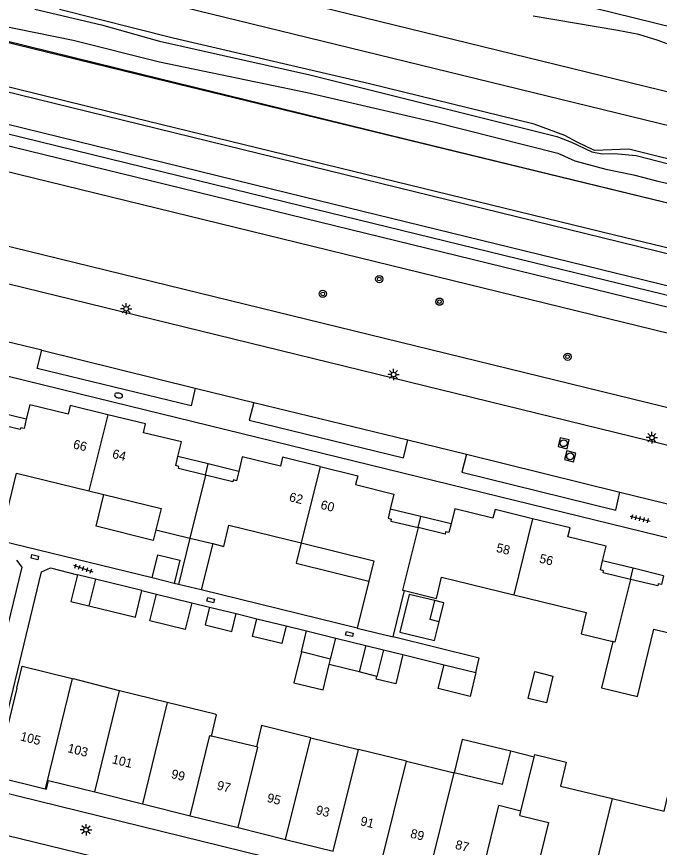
# Model space of a CAD drawing. Extents: x 125000 to 129004, y 397500 to 399008.
# Drawn here: x 126519.7 to 126590.3, y 398569.4 to 398660.6 of the extents above; entities that cross this region are included whole.
import ezdxf

# ---------------------------------------------------------------- set-up
doc = ezdxf.new("R2010")
doc.units = 0
for name, color, linetype in [('gg-afsc-erfafscheiding', 7, 'Continuous'), ('gg-afsc-hekwerk', 7, 'Continuous'), ('gg-anno-huisnummerreeks BGT', 7, 'Continuous'), ('gg-aspt-spoorlijn', 7, 'Continuous'), ('gg-bbg-bijgebouw', 7, 'Continuous'), ('gg-bbg-gedigitaliseerde bebouwing', 7, 'Continuous'), ('gg-bbg-gedigitaliseerde bijgebouw', 7, 'Continuous'), ('gg-bbg-hoofdgebouw', 7, 'Continuous'), ('gg-bbg-luifel en loopbrug', 7, 'Continuous'), ('gg-bbg-tussenscheiding', 7, 'Continuous'), ('gg-knt-BGT kruinlijn', 7, 'Continuous'), ('gg-knt-verharding', 7, 'Continuous'), ('gg-knt-verharding nz', 7, 'Continuous'), ('gg-kntw-bovenkant insteek waterloop', 7, 'Continuous'), ('gg-kntw-waterlijn', 7, 'Continuous'), ('gt-grn-groengrens', 7, 'Continuous'), ('gt-symb-boom', 7, 'Continuous'), ('gt-symb-brandkraan', 7, 'Continuous'), ('gt-symb-kolk center center', 7, 'Continuous'), ('gt-symb-lichtmast', 7, 'Continuous'), ('gt-symb-rioolschacht', 7, 'Continuous'), ('gt-symb-tegel verharding', 7, 'Continuous'), ('gx-grn-maaiveld', 7, 'Continuous')]:
    doc.layers.add(name, color=color, linetype=linetype)

# ---------------------------------------------------------------- blocks, each defined once
blk = doc.blocks.new('gt0-LMAST')
at = {"layer": 'gt-symb-lichtmast'}
for p, q in [((-0.182, 0.173), (-0.447, 0.438)), ((-0.005, 0.246), (-0.005, 0.621)), ((0.172, 0.173), (0.437, 0.438)), ((-0.255, -0.004), (-0.63, -0.004)), ((-0.182, -0.181), (-0.447, -0.446)), ((-0.005, -0.254), (-0.005, -0.629)), ((0.437, -0.446), (0.172, -0.181)), ((0.245, -0.004), (0.62, -0.004))]:
    blk.add_line(p, q, dxfattribs=at)
blk.add_circle((-0.005, -0.004), 0.25, dxfattribs=at)
blk = doc.blocks.new('gt0-KOLKCC')
at = {"layer": 'gt-symb-kolk center center'}
blk.add_lwpolyline([(-0.375, 0.2), (0.375, 0.2), (0.375, -0.2), (-0.375, -0.2)], close=True, dxfattribs=at)
blk = doc.blocks.new('gt0-TEG1')
at = {"layer": 'gt-symb-tegel verharding'}
for p, q in [((-1.125, 0), (1.125, 0)), ((-0.9, -0.25), (-0.9, 0.25)), ((-0.45, -0.25), (-0.45, 0.25)), ((0, -0.25), (0, 0.25)), ((0.45, -0.25), (0.45, 0.25)), ((0.9, -0.25), (0.9, 0.25))]:
    blk.add_line(p, q, dxfattribs=at)
blk = doc.blocks.new('gt0-RS')
at = {"layer": 'gt-symb-rioolschacht'}
blk.add_lwpolyline([(-0.5, -0.5), (0.5, -0.5), (0.5, 0.5), (-0.5, 0.5)], close=True, dxfattribs=at)
blk.add_circle((0, 0), 0.375, dxfattribs=at)
blk = doc.blocks.new('gt0-BOOM')
at = {"layer": 'gt-symb-boom'}
for radius in [0.4, 0.2]:
    blk.add_circle((0, 0), radius, dxfattribs=at)
blk = doc.blocks.new('gt0-BR')
at = {"layer": 'gt-symb-brandkraan'}
for centre, radius, start, end in [((-0.244, 0), 0.206, 107.56694, 252.43307), ((0.599, -2.664), 3, 106.89205, 107.56694), ((0, -0.691), 0.938, 73.10799, 106.89205), ((-0.599, -2.664), 3, 72.43309, 73.10799), ((0.244, 0), 0.206, 287.56695, 72.43309), ((0.599, 2.664), 3, 252.43307, 253.10797), ((0, 0.691), 0.938, 253.10797, 286.89206), ((-0.599, 2.664), 3, 286.89206, 287.56695)]:
    blk.add_arc(centre, radius, start, end, dxfattribs=at)

msp = doc.modelspace()

# ---------------------------------------------------------------- linework, layer by layer
at = {"layer": 'gg-afsc-erfafscheiding'}
for p, q in [((126534.591, 398598.969), (126517.906, 398603.051)), ((126537.488, 398598.26), (126537.02, 398598.375)), ((126557.101, 398593.463), (126539.996, 398597.647)), ((126533.482, 398597.58), (126535.067, 398597.191)), ((126538.952, 398596.239), (126540.894, 398595.763)), ((126543.808, 398595.048), (126546.091, 398594.488)), ((126549.296, 398593.702), (126551.542, 398593.151)), ((126562.128, 398590.554), (126566.636, 398589.448))]:
    msp.add_line(p, q, dxfattribs=at)
for points in [[(126519.71, 398600.927), (126520.306, 398600.163), (126514.596, 398576.815), (126514.448, 398576.329)], [(126516.671, 398575.792), (126522.462, 398599.626), (126523.459, 398600.086), (126526.396, 398599.321)], [(126570.132, 398588.591), (126570.497, 398590.181), (126561.049, 398592.494)]]:
    msp.add_lwpolyline(points, dxfattribs=at)
at = {"layer": 'gg-afsc-hekwerk'}
msp.add_line((126650.035, 398603.269), (126463.135, 398648.945), dxfattribs=at)
for points in [[(126940.304, 398557.446), (126936.567, 398555.946), (126917.248, 398560.73), (126904.597, 398563.825), (126899.09, 398565.16), (126880.395, 398569.39), (126871.244, 398571.606), (126843.113, 398578.463), (126834.208, 398580.63), (126815.394, 398585.233), (126798.941, 398589.25), (126780.443, 398593.783), (126766.856, 398597.149), (126719.035, 398608.855), (126669.566, 398620.853), (126627.707, 398631.15), (126610.862, 398635.296), (126560.721, 398647.519), (126548.679, 398650.481), (126533.314, 398654.267), (126513.26, 398659.192), (126493.962, 398663.952), (126437.616, 398677.701), (126422.794, 398681.33)], [(126461.9, 398657.483), (126656.147, 398609.937), (126654.287, 398602.23)]]:
    msp.add_lwpolyline(points, dxfattribs=at)
at = {"layer": 'gg-aspt-spoorlijn'}
for points in [[(126178.191, 398753.482), (126243.646, 398737.457), (126261.198, 398733.101), (126493.406, 398676.338), (126551.442, 398662.053), (126716.835, 398621.637), (126769.514, 398608.681), (126782.186, 398605.654), (126808.742, 398599.06), (126873.678, 398583.156), (126950.767, 398564.393)], [(126177.482, 398749.914), (126237.61, 398735.207), (126282.856, 398724.218), (126424.134, 398689.529), (126477.102, 398676.62), (126493.227, 398672.592), (126610.16, 398643.995), (126627.72, 398639.762), (126691.525, 398624.102), (126709.464, 398619.631), (126949.829, 398560.886)]]:
    msp.add_lwpolyline(points, dxfattribs=at)
at = {"layer": 'gg-bbg-bijgebouw'}
msp.add_line((126528.382, 398598.831), (126526.396, 398599.321), dxfattribs=at)
for points in [[(126526.396, 398599.321), (126525.681, 398596.371), (126527.673, 398595.889)], [(126576.602, 398588.69), (126578.591, 398588.197), (126577.86, 398585.247), (126575.87, 398585.741), (126576.602, 398588.69)]]:
    msp.add_lwpolyline(points, dxfattribs=at)
at = {"layer": 'gg-bbg-gedigitaliseerde bebouwing'}
for p, q in [((126573.052, 398576.282), (126573.95, 398579.944)), ((126576.517, 398579.315), (126573.95, 398579.944)), ((126576.517, 398579.315), (126576.588, 398579.606)), ((126567.736, 398577.595), (126567.582, 398577.633)), ((126573.052, 398576.282), (126567.736, 398577.595)), ((126570.261, 398564.268), (126572.642, 398573.978)), ((126575.067, 398573.384), (126572.642, 398573.978)), ((126574.948, 398572.898), (126575.067, 398573.384))]:
    msp.add_line(p, q, dxfattribs=at)
at = {"layer": 'gg-bbg-gedigitaliseerde bijgebouw'}
for p, q in [((126533.482, 398597.58), (126528.382, 398598.831)), ((126537.02, 398598.375), (126534.591, 398598.969)), ((126535.067, 398597.191), (126538.952, 398596.239)), ((126540.894, 398595.763), (126543.808, 398595.048)), ((126546.091, 398594.488), (126549.296, 398593.702)), ((126550.975, 398590.842), (126551.542, 398593.151)), ((126551.542, 398593.151), (126554.746, 398592.365)), ((126554.746, 398592.365), (126558.049, 398591.555)), ((126558.049, 398591.555), (126557.335, 398588.647)), ((126554.18, 398590.055), (126550.975, 398590.842)), ((126559.991, 398591.078), (126559.277, 398588.17)), ((126559.991, 398591.078), (126562.128, 398590.554)), ((126554.033, 398589.457), (126554.18, 398590.055)), ((126557.335, 398588.647), (126554.033, 398589.457)), ((126566.636, 398589.448), (126570.132, 398588.591))]:
    msp.add_line(p, q, dxfattribs=at)
for points in [[(126534.591, 398598.969), (126535.211, 398601.496), (126537.639, 398600.901), (126537.02, 398598.375)], [(126527.673, 398595.889), (126532.774, 398594.655), (126533.482, 398597.58)], [(126538.952, 398596.239), (126538.237, 398593.325), (126534.352, 398594.278), (126535.067, 398597.191)], [(126565.638, 398596.475), (126562.812, 398597.167), (126561.796, 398593.019)], [(126566.102, 398594.164), (126565.13, 398594.401), (126565.638, 398596.475)], [(126540.894, 398595.763), (126540.418, 398593.82), (126543.332, 398593.106), (126543.808, 398595.048)], [(126549.296, 398593.702), (126548.82, 398591.759), (126545.615, 398592.545), (126546.091, 398594.488)], [(126561.796, 398593.019), (126565.594, 398592.09), (126566.102, 398594.164)], [(126562.128, 398590.554), (126561.342, 398587.349), (126559.204, 398587.873), (126559.277, 398588.17)], [(126570.132, 398588.591), (126569.489, 398585.969), (126565.993, 398586.826), (126566.636, 398589.448)]]:
    msp.add_lwpolyline(points, dxfattribs=at)
at = {"layer": 'gg-bbg-hoofdgebouw'}
for p, q in [((126527.656, 398608.526), (126529.304, 398608.122)), ((126535.017, 398604.26), (126538.737, 398603.348)), ((126538.737, 398603.348), (126541.245, 398602.733)), ((126558.367, 398598.625), (126557.101, 398593.463)), ((126561.049, 398592.494), (126562.298, 398597.583)), ((126557.101, 398593.463), (126561.049, 398592.494)), ((126525.824, 398587.944), (126525.963, 398587.91)), ((126530.869, 398586.617), (126525.963, 398587.91)), ((126531.024, 398586.579), (126530.869, 398586.617)), ((126536.267, 398585.291), (126531.024, 398586.579)), ((126541.521, 398584), (126536.267, 398585.291)), ((126552.028, 398581.431), (126546.766, 398582.72)), ((126546.052, 398580.432), (126541.113, 398581.622)), ((126552.028, 398581.431), (126557.243, 398580.156)), ((126562.508, 398578.866), (126557.243, 398580.156)), ((126562.508, 398578.866), (126567.582, 398577.633)), ((126528.3, 398575.49), (126533.543, 398574.184)), ((126533.543, 398574.184), (126538.782, 398572.879)), ((126538.782, 398572.879), (126544.033, 398571.571)), ((126544.033, 398571.571), (126549.253, 398570.271)), ((126549.253, 398570.271), (126554.483, 398568.969))]:
    msp.add_line(p, q, dxfattribs=at)
for points in [[(126529.745, 398616.886), (126525.618, 398617.903), (126525.379, 398616.934), (126521.18, 398617.969), (126520.797, 398616.383)], [(126537.431, 398612.284), (126537.821, 398613.896), (126533.638, 398614.901), (126533.871, 398615.869), (126529.745, 398616.886)], [(126520.797, 398616.383), (126520.55, 398615.362), (126520.179, 398615.448), (126520.138, 398615.27), (126517.168, 398615.97)], [(126540.467, 398610.249), (126537.484, 398610.971), (126537.54, 398611.205), (126537.19, 398611.29), (126537.431, 398612.284)], [(126553.044, 398611.191), (126548.919, 398612.204), (126548.68, 398611.232), (126544.492, 398612.242), (126544.115, 398610.657)], [(126517.906, 398603.051), (126519.726, 398610.471), (126527.656, 398608.526)], [(126544.115, 398610.657), (126543.87, 398609.628), (126543.517, 398609.739), (126543.45, 398609.527), (126540.467, 398610.249)], [(126553.044, 398611.191), (126557.169, 398610.177), (126556.925, 398609.205), (126561.125, 398608.149), (126560.734, 398606.529)], [(126529.304, 398608.122), (126535.586, 398606.581), (126535.017, 398604.26)], [(126560.734, 398606.529), (126560.491, 398605.521), (126560.849, 398605.434), (126560.796, 398605.211), (126563.781, 398604.491)], [(126576.355, 398605.472), (126572.235, 398606.491), (126571.995, 398605.521), (126567.812, 398606.556), (126567.409, 398604.904)], [(126584.028, 398600.848), (126584.414, 398602.449), (126580.236, 398603.483), (126580.475, 398604.452), (126576.355, 398605.472)], [(126541.245, 398602.733), (126542.457, 398602.435), (126543.026, 398604.756), (126550.971, 398602.808)], [(126567.409, 398604.904), (126567.176, 398603.948), (126566.813, 398604.019), (126566.765, 398603.77), (126563.781, 398604.491)], [(126550.971, 398602.808), (126558.915, 398600.859), (126558.367, 398598.625)], [(126587.085, 398598.808), (126584.083, 398599.531), (126584.137, 398599.756), (126583.786, 398599.841), (126584.028, 398600.848)], [(126562.298, 398597.583), (126565.794, 398596.726), (126566.366, 398599.057), (126574.301, 398597.111)], [(126590.733, 398599.216), (126590.502, 398598.25), (126590.14, 398598.33), (126590.086, 398598.085), (126587.085, 398598.808)], [(126574.301, 398597.111), (126582.236, 398595.164), (126581.666, 398592.843), (126585.153, 398591.988)], [(126585.153, 398591.988), (126583.907, 398586.908), (126587.854, 398585.942), (126589.659, 398593.337), (126597.594, 398591.401)], [(126519.752, 398586.855), (126520.348, 398589.277), (126525.824, 398587.944)], [(126519.752, 398586.855), (126517.375, 398577.173), (126522.858, 398575.839)], [(126541.113, 398581.622), (126541.677, 398583.962), (126541.521, 398584)], [(126546.766, 398582.72), (126546.612, 398582.758), (126546.052, 398580.432)], [(126576.588, 398579.606), (126580.037, 398578.76), (126579.397, 398576.134), (126585.09, 398574.746)], [(126522.858, 398575.839), (126523.014, 398575.801), (126523.244, 398576.749), (126528.3, 398575.49)], [(126585.09, 398574.746), (126590.782, 398573.357), (126591.43, 398575.972), (126594.764, 398575.162)], [(126574.948, 398572.898), (126578.089, 398572.127), (126575.821, 398562.888), (126580.365, 398561.78), (126580.56, 398562.553), (126582.031, 398562.198)]]:
    msp.add_lwpolyline(points, dxfattribs=at)
at = {"layer": 'gg-bbg-luifel en loopbrug'}
for p, q in [((126520.797, 398616.383), (126517.466, 398617.194)), ((126540.765, 398611.473), (126537.431, 398612.284)), ((126540.467, 398610.249), (126540.765, 398611.473)), ((126544.115, 398610.657), (126540.765, 398611.473)), ((126564.079, 398605.715), (126560.734, 398606.529)), ((126563.781, 398604.491), (126564.079, 398605.715)), ((126567.409, 398604.904), (126564.079, 398605.715)), ((126538.737, 398603.348), (126537.488, 398598.26)), ((126541.245, 398602.733), (126539.996, 398597.647)), ((126587.383, 398600.032), (126584.028, 398600.848)), ((126587.085, 398598.808), (126587.383, 398600.032)), ((126590.733, 398599.216), (126587.383, 398600.032)), ((126539.996, 398597.647), (126537.488, 398598.26)), ((126558.049, 398591.555), (126559.991, 398591.078)), ((126559.277, 398588.17), (126557.335, 398588.647))]:
    msp.add_line(p, q, dxfattribs=at)
for points in [[(126535.017, 398604.26), (126534.731, 398603.095), (126528.449, 398604.636), (126529.304, 398608.122)], [(126550.971, 398602.808), (126550.423, 398600.574), (126558.367, 398598.625)], [(126566.102, 398594.164), (126566.609, 398596.238), (126565.638, 398596.475)], [(126550.975, 398590.842), (126550.148, 398587.472), (126553.353, 398586.685), (126554.033, 398589.457)], [(126573.95, 398579.944), (126568.632, 398581.248), (126567.736, 398577.595)]]:
    msp.add_lwpolyline(points, dxfattribs=at)
at = {"layer": 'gg-bbg-tussenscheiding'}
for p, q in [((126529.745, 398616.886), (126527.656, 398608.526)), ((126553.044, 398611.191), (126550.971, 398602.808)), ((126540.467, 398610.249), (126538.737, 398603.348)), ((126576.355, 398605.472), (126574.301, 398597.111)), ((126528.382, 398598.831), (126527.673, 398595.889)), ((126554.18, 398590.055), (126554.746, 398592.365)), ((126525.824, 398587.944), (126522.858, 398575.839)), ((126528.3, 398575.49), (126531.024, 398586.579)), ((126536.267, 398585.291), (126533.543, 398574.184)), ((126549.253, 398570.271), (126552.028, 398581.431)), ((126554.483, 398568.969), (126557.243, 398580.156)), ((126559.723, 398567.664), (126562.508, 398578.866)), ((126575.067, 398573.384), (126576.517, 398579.315)), ((126564.778, 398565.596), (126567.736, 398577.595)), ((126585.09, 398574.746), (126582.031, 398562.198))]:
    msp.add_line(p, q, dxfattribs=at)
for points in [[(126563.781, 398604.491), (126562.085, 398597.635), (126562.298, 398597.583)], [(126587.085, 398598.808), (126585.395, 398591.929), (126585.153, 398591.988)], [(126538.782, 398572.879), (126540.945, 398581.662), (126541.113, 398581.622)], [(126544.033, 398571.571), (126546.197, 398580.397), (126546.052, 398580.432)]]:
    msp.add_lwpolyline(points, dxfattribs=at)
at = {"layer": 'gg-knt-BGT kruinlijn'}
for p, q in [((126521.747, 398661.383), (126529.045, 398659.683)), ((126529.045, 398659.683), (126535.417, 398657.866)), ((126535.417, 398657.866), (126551.91, 398654.192)), ((126551.91, 398654.192), (126579.029, 398647.415)), ((126579.029, 398647.415), (126580.627, 398646.792)), ((126580.627, 398646.792), (126582.844, 398645.725)), ((126582.844, 398645.725), (126583.995, 398645.505)), ((126583.995, 398645.505), (126585.287, 398645.546)), ((126585.287, 398645.546), (126587.706, 398645.315)), ((126587.706, 398645.315), (126615.518, 398638.303))]:
    msp.add_line(p, q, dxfattribs=at)
at = {"layer": 'gg-knt-verharding'}
for p, q in [((126522.481, 398623.957), (126516.06, 398625.5)), ((126539.325, 398619.806), (126545.748, 398618.233)), ((126562.67, 398614.11), (126569.099, 398612.538)), ((126585.94, 398608.385), (126592.369, 398606.797)), ((126618.701, 398550.799), (126516.671, 398575.792))]:
    msp.add_line(p, q, dxfattribs=at)
for points in [[(126410.563, 398647.575), (126475.229, 398631.783), (126528.498, 398618.73), (126646.676, 398589.816)], [(126459.086, 398645.884), (126561.031, 398620.941), (126618.703, 398606.814), (126649.066, 398599.42)], [(126539.325, 398619.806), (126538.885, 398617.845), (126522.002, 398621.965), (126522.481, 398623.957)], [(126545.748, 398618.233), (126545.265, 398616.278), (126562.19, 398612.15), (126562.67, 398614.11)], [(126569.099, 398612.538), (126568.602, 398610.561), (126585.483, 398606.411), (126585.94, 398608.385)], [(126532.704, 398567.274), (126518.629, 398570.719), (126516.855, 398571.13)]]:
    msp.add_lwpolyline(points, dxfattribs=at)
at = {"layer": 'gg-knt-verharding nz'}
for p, q in [((126522.481, 398623.957), (126539.325, 398619.806)), ((126545.748, 398618.233), (126562.67, 398614.11)), ((126569.099, 398612.538), (126585.94, 398608.385))]:
    msp.add_line(p, q, dxfattribs=at)
at = {"layer": 'gg-kntw-bovenkant insteek waterloop'}
for points in [[(126884.78, 398555.055), (126883.859, 398556.325), (126882.317, 398558.95), (126881.397, 398561.406), (126880.656, 398563.893), (126880.292, 398564.441), (126879.702, 398564.704), (126835.226, 398575.342), (126811.696, 398581.072), (126777.541, 398589.594), (126703.282, 398607.867), (126666.097, 398616.844), (126628.82, 398626.095), (126585.331, 398636.579), (126532.543, 398649.474), (126439.89, 398672.318), (126413.91, 398678.645), (126371.611, 398689.132), (126335.87, 398697.677), (126320.19, 398701.725), (126299.052, 398706.82)], [(126416.244, 398672.929), (126432.133, 398669.072), (126510.587, 398649.723), (126549.24, 398640.255), (126624.257, 398621.922), (126650.985, 398615.296), (126659.461, 398613.222)]]:
    msp.add_lwpolyline(points, dxfattribs=at)
at = {"layer": 'gg-kntw-waterlijn'}
for points in [[(126883.756, 398554.584), (126880.055, 398560.293), (126879.898, 398563.062), (126879.574, 398563.639), (126797.66, 398583.721), (126685.639, 398611.52), (126682.195, 398612.211), (126648.017, 398620.572), (126585.914, 398635.811), (126503.077, 398656.117), (126501.543, 398656.238), (126379.063, 398686.457), (126319.783, 398700.897), (126277.973, 398711.201), (126206.215, 398728.88), (126204.896, 398727.907)], [(126416.48, 398673.901), (126432.371, 398670.043), (126510.826, 398650.694), (126549.478, 398641.226), (126624.496, 398622.893), (126651.224, 398616.267), (126659.699, 398614.193)]]:
    msp.add_lwpolyline(points, dxfattribs=at)
at = {"layer": 'gt-grn-groengrens'}
msp.add_lwpolyline([(126686.829, 398601.086), (126686.71, 398601.196), (126682.165, 398605.078), (126680.031, 398606.481), (126677.259, 398607.61), (126447.199, 398663.906), (126441.156, 398663.817), (126431.621, 398662.572), (126425.661, 398661.08), (126423.684, 398661.001), (126421.639, 398661.453), (126402.312, 398666.071), (126399.561, 398667.314), (126397.23, 398669.459), (126394.183, 398671.219), (126391.793, 398671.729), (126378.802, 398671.135), (126378.013, 398671.207)], dxfattribs=at)
at = {"layer": 'gx-grn-maaiveld'}
for points in [[(126945.927, 398557.564), (126940.252, 398557.417), (126936.408, 398555.941), (126907.634, 398563.051), (126876.581, 398570.191), (126834.489, 398580.656), (126763.757, 398597.745), (126719.035, 398608.855), (126669.566, 398620.853), (126626.549, 398631.511), (126534.826, 398653.762), (126386.268, 398690.139), (126340.179, 398701.514), (126290.598, 398713.583)], [(126858.567, 398594.62), (126855.761, 398595.557), (126851.028, 398596.414), (126845.51, 398597.641), (126739.049, 398623.035), (126699.561, 398633.66), (126630.673, 398649.797), (126535.347, 398673.269), (126517.497, 398677.814), (126400.313, 398706.597)], [(126513.309, 398660.723), (126515.551, 398660.184), (126517.817, 398659.649), (126525.92, 398657.994), (126535.421, 398655.594), (126551.63, 398652.249), (126565.515, 398649.009), (126579.104, 398645.58), (126580.99, 398644.74), (126584.384, 398643.844), (126587.417, 398643.193), (126590.088, 398642.505), (126595.519, 398641.3)], [(126633.37, 398634.472), (126586.896, 398646.009), (126583.154, 398645.873), (126581.257, 398646.778), (126579.887, 398647.534), (126576.514, 398648.749), (126558.472, 398653.195), (126536.92, 398658.21), (126524.439, 398661.35)], [(126593.29, 398656.778), (126590.138, 398657.944), (126587.998, 398658.597), (126585.693, 398659.055), (126576.418, 398660.621)]]:
    msp.add_lwpolyline(points, dxfattribs=at)

# ---------------------------------------------------------------- block references
at = {"layer": 'gt-symb-boom'}
for p in [(126559.528, 398631.766), (126553.324, 398630.14), (126566.131, 398629.287), (126580.195, 398623.245)]:
    msp.add_blockref('gt0-BOOM', p, dxfattribs=at)
at = {"layer": 'gt-symb-brandkraan', "rotation": -11.006664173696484}
msp.add_blockref('gt0-BR', (126530.921, 398618.994), dxfattribs=at)
at = {"layer": 'gt-symb-kolk center center'}
for p, rotation in [((126521.732, 398601.25), 166.4084395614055), ((126541.025, 398596.536), -13.71646932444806), ((126556.246, 398592.804), -12.006708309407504)]:
    msp.add_blockref('gt0-KOLKCC', p, dxfattribs=dict(at, rotation=rotation))
at = {"layer": 'gt-symb-lichtmast'}
for p in [(126531.762, 398628.508), (126561.104, 398621.301), (126589.455, 398614.368), (126527.35, 398571.323)]:
    msp.add_blockref('gt0-LMAST', p, dxfattribs=at)
at = {"layer": 'gt-symb-rioolschacht'}
for p, rotation in [((126579.761, 398613.756), 166.64465903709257), ((126580.472, 398612.316), 165.40804379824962)]:
    msp.add_blockref('gt0-RS', p, dxfattribs=dict(at, rotation=rotation))
at = {"layer": 'gt-symb-tegel verharding'}
for p, rotation in [((126588.149, 398605.479), -13.772145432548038), ((126527.043, 398600.009), -18.362468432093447)]:
    msp.add_blockref('gt0-TEG1', p, dxfattribs=dict(at, rotation=rotation))

# ---------------------------------------------------------------- texts
at = {"layer": 'gg-anno-huisnummerreeks BGT'}
for s, rotation, p in [('66', 346.2, (126525.86, 398613.207)), ('64', 346.2, (126530.158, 398612.148)), ('62', 346.2, (126549.566, 398607.411)), ('60', 346.2, (126553.017, 398606.563)), ('58', 346.1, (126572.292, 398601.842)), ('56', 346.1, (126577.023, 398600.672)), ('105', 346, (126520.068, 398581.148)), ('103', 346, (126525.252, 398579.856)), ('101', 346, (126530.134, 398578.641)), ('99', 346, (126536.62, 398577.025)), ('97', 346, (126541.64, 398575.774)), ('95', 346, (126547.139, 398574.405)), ('93', 346, (126552.498, 398573.07)), ('91', 346, (126557.38, 398571.855)), ('89', 346, (126562.869, 398570.487)), ('87', 346, (126567.794, 398569.26))]:
    msp.add_text(s, height=1, rotation=rotation, dxfattribs=at).set_placement(p)

doc.saveas('drawing.dxf')
